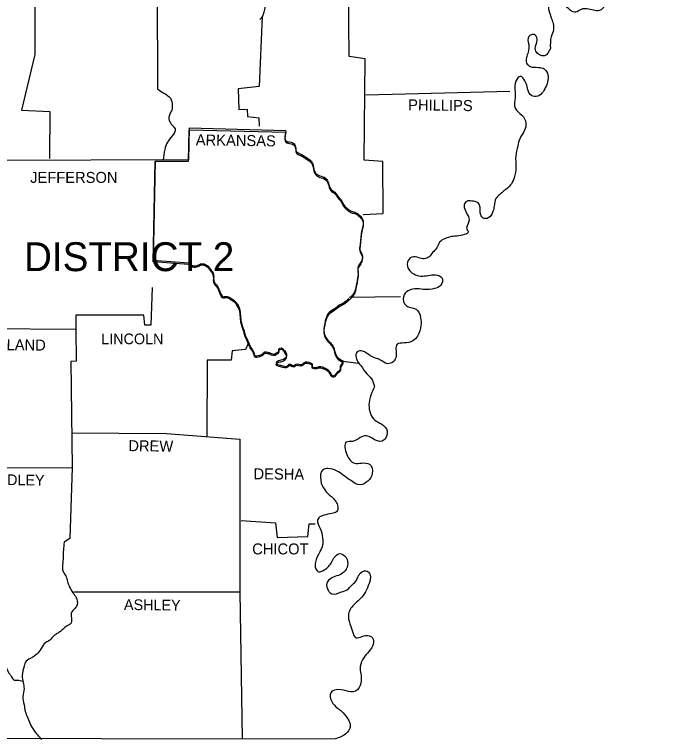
# Model space of a CAD drawing. Extents: x 172 to 3385, y 73 to 2074.
# Drawn here: x 3005.2 to 3257.2, y 1432.7 to 1710.1 of the extents above; entities that cross this region are included whole.
import ezdxf

# ---------------------------------------------------------------- set-up
doc = ezdxf.new("R2010")
doc.units = 0
for name, color, linetype in [('R_Border', 7, 'Continuous'), ('R_Border Prem', 7, 'Continuous'), ('R_Grid', 7, 'Continuous')]:
    doc.layers.add(name, color=color, linetype=linetype)

msp = doc.modelspace()

# ---------------------------------------------------------------- linework, layer by layer
at = {"layer": 'R_Border Prem'}
msp.add_line((3133.42, 1601.94), (3152.99, 1602.24), dxfattribs=at)
for points in [[(3045.86, 1737.06), (3046.05, 1719.55), (3059.85, 1719.25), (3059.95, 1681.68)], [(3007.21, 1732.56), (3012.88, 1732.17), (3012.98, 1694.79), (3007.89, 1673.56), (3018.75, 1673.07), (3018.66, 1655.07)], [(3138.71, 1633.54), (3146.34, 1634.03), (3146.24, 1653.9), (3139.1, 1654.38), (3139.49, 1693.23), (3133.33, 1694.11), (3133.13, 1720.23), (3216.59, 1720.82)], [(3100.06, 1709.37), (3098.89, 1682.56), (3090.86, 1681.68), (3091.06, 1673.76), (3094.29, 1673.85), (3094.39, 1671.11), (3098.79, 1670.63), (3098.89, 1667.4)], [(3139.69, 1679.43), (3194.87, 1680.8)], [(3109.06, 1665.64), (3072.08, 1666.61), (3071.88, 1654.58), (2997.03, 1654.29)], [(3059.06, 1653.99), (3071.88, 1653.99), (3072.08, 1666.03), (3109.06, 1665.05)], [(3059.06, 1653.99), (3058.28, 1616.13), (3071.88, 1615.05)], [(3071.88, 1614.47), (3058.28, 1615.54), (3059.06, 1653.99)], [(3057.99, 1605.66), (3057.4, 1591.28), (3055.15, 1591.28), (3054.76, 1595.09), (3028.73, 1595.09), (3028.73, 1589.61)], [(2993.9, 1589.91), (3028.54, 1589.71)], [(3028.73, 1589.71), (3028.83, 1577.48), (3026.78, 1577.38), (3027.36, 1536.78)], [(3094.87, 1584.53), (3093.7, 1581.88), (3088.51, 1581.4), (3088.22, 1577.87), (3078.93, 1577.87), (3078.83, 1548.62)], [(3105.83, 1580.22), (3106.13, 1580.51), (3106.42, 1580.81), (3106.42, 1580.81)], [(3027.07, 1550.09), (3063.37, 1549.79), (3091.55, 1547.64)], [(3091.55, 1547.64), (3091.55, 1489.13), (3092.33, 1432.87)], [(2983.14, 1536.68), (3027.36, 1536.78)], [(3027.36, 1536.78), (3026.39, 1509.58), (3024.23, 1508.21)], [(3092.04, 1516.43), (3105.15, 1515.65), (3105.73, 1509.97), (3117.57, 1510.36), (3118.06, 1515.16), (3120.31, 1515.16)], [(2769.26, 1512.61), (2769.46, 1433.46), (3128.04, 1432.87)], [(3027.95, 1489.23), (3091.55, 1489.23)]]:
    msp.add_lwpolyline(points, dxfattribs=at)
for points in [[(3252.89, 1794.1), (3253.28, 1791.26), (3251.62, 1788.23), (3251.03, 1785.2), (3251.32, 1782.16), (3248.19, 1780.5), (3245.45, 1778.54), (3247.02, 1776.2), (3249.95, 1774.04), (3252.89, 1772.38), (3254.75, 1770.72), (3255.24, 1766.71), (3255.72, 1764.16), (3256.7, 1760.64), (3257.09, 1758.19), (3255.33, 1755.26), (3253.28, 1754.67), (3251.13, 1755.36), (3248.58, 1755.55), (3246.53, 1753.59), (3245.06, 1750.86), (3243.59, 1748.12), (3242.52, 1745.77), (3241.44, 1743.22), (3239.29, 1740.29), (3236.65, 1739.8), (3233.51, 1739.02), (3231.66, 1736.86), (3231.95, 1733.24), (3233.71, 1730.8), (3235.08, 1727.76), (3236.06, 1725.12), (3235.57, 1721.8), (3234.2, 1719.35), (3232.44, 1717.88), (3231.66, 1714.75), (3230.38, 1712.4), (3229.21, 1711.62), (3226.86, 1711.82), (3224.32, 1712.31), (3222.16, 1712.11), (3220.11, 1711.03), (3218.06, 1711.72), (3215.9, 1714.07), (3214.14, 1715.83), (3212.19, 1716.51), (3210.13, 1715.44), (3209.74, 1712.21), (3210.72, 1708.88), (3211.6, 1704.38), (3210.72, 1701.64), (3210.42, 1697.14)], [(3098.98, 1718.76), (3098.59, 1716.81), (3099.37, 1714.75), (3100.74, 1714.07), (3100.94, 1712.11), (3100.45, 1710.15), (3100.06, 1709.37), (3099.18, 1708.2)], [(3210.42, 1697.14), (3208.17, 1694.3), (3204.85, 1696.06), (3204.85, 1698.41), (3205.34, 1700.86), (3204.16, 1702.42), (3202.11, 1701.74), (3202.11, 1698.71), (3201.91, 1695.77), (3201.32, 1691.56), (3202.69, 1690.29), (3205.83, 1689.9), (3208.08, 1689.31), (3209.45, 1687.06), (3209.35, 1684.32), (3208.27, 1681.68), (3206.71, 1679.53), (3204.26, 1678.75), (3202.3, 1680.02), (3201.52, 1682.56), (3200.64, 1684.81), (3198.98, 1686.48), (3197.22, 1684.62), (3196.82, 1681.19), (3196.92, 1678.26), (3196.92, 1674.25), (3199.47, 1671.6), (3201.03, 1668.57), (3200.54, 1665.83), (3198.68, 1662.6), (3197.9, 1659.77), (3197.12, 1655.95), (3197.22, 1651.74), (3196.53, 1647.63), (3195.16, 1644.89), (3192.62, 1642.64), (3190.95, 1641.18), (3189.58, 1639.71), (3188.9, 1636.77), (3188.41, 1634.72), (3186.55, 1632.27), (3185.08, 1632.08), (3183.91, 1633.05), (3183.52, 1634.72), (3183.52, 1636.38), (3182.74, 1638.04), (3180.29, 1638.73), (3178.33, 1638.63), (3177.45, 1637.26), (3178.72, 1633.45), (3179.21, 1631), (3178.53, 1627.67), (3178.92, 1627.28), (3175.4, 1625.42), (3172.56, 1625.13), (3170.21, 1624.44), (3167.96, 1622.98), (3166.88, 1620.82), (3165.32, 1619.06), (3163.95, 1617.4), (3162.09, 1616.62), (3160.04, 1617.01), (3157.3, 1617.3), (3155.73, 1615.35), (3156.22, 1612.51), (3158.08, 1610.85), (3160.82, 1610.06), (3163.66, 1610.26), (3166.4, 1610.55), (3168.94, 1609.18), (3168.45, 1606.54), (3166, 1605.27), (3162.38, 1604.88), (3159.45, 1605.17), (3155.93, 1604.39), (3154.17, 1602.14), (3155.14, 1598.71), (3158.96, 1597.34), (3160.72, 1594.11), (3160.82, 1591.08), (3159.55, 1587.07), (3157.79, 1585.21), (3154.36, 1584.43), (3151.72, 1583.94), (3151.33, 1579.44), (3150.15, 1577.19), (3148.1, 1576.5), (3145.16, 1577.97), (3143.4, 1578.66), (3141.25, 1579.63), (3138.51, 1581.3), (3136.46, 1581), (3137.04, 1576.7), (3137.24, 1576.5), (3139.59, 1573.27), (3141.94, 1570.73), (3143.01, 1567.7)], [(3059.95, 1681.68), (3062.39, 1680.02), (3064.93, 1678.06), (3065.62, 1675.42), (3065.42, 1673.56), (3064.64, 1672), (3064.45, 1669.55), (3065.62, 1667.79), (3066.7, 1666.32), (3065.62, 1663.68), (3063.76, 1661.23), (3062.78, 1658.49), (3062.1, 1654.38)], [(3109.06, 1665.64), (3109.35, 1661.62), (3111.7, 1661.04), (3112.68, 1659.96), (3113.17, 1657.71), (3114.83, 1656.73), (3117.08, 1655.36), (3118.45, 1654.38), (3119.43, 1652.82), (3120.02, 1650.27), (3121.58, 1648.61), (3123.74, 1647.83), (3125.3, 1645.97), (3126.28, 1643.33), (3127.85, 1642.15), (3129.41, 1640.1), (3130.19, 1639.22), (3131.56, 1636.87), (3132.93, 1635.7), (3133.91, 1635.01), (3135.48, 1634.52), (3137.43, 1633.25), (3138.71, 1631.29), (3138.71, 1629.83), (3138.22, 1627.58), (3137.83, 1625.23), (3137.63, 1622.59), (3137.43, 1620.24), (3138.32, 1618.28), (3137.83, 1615.35), (3136.85, 1613.78), (3136.75, 1611.63), (3136.46, 1608.4), (3136.07, 1606.54), (3135.18, 1603.51), (3133.91, 1601.94)], [(3109.06, 1665.05), (3109.35, 1661.04), (3111.7, 1660.45), (3112.68, 1659.37), (3113.17, 1657.12), (3114.83, 1656.15), (3117.08, 1654.78), (3118.45, 1653.8), (3119.43, 1652.23), (3120.02, 1649.69), (3121.58, 1648.02), (3123.74, 1647.24), (3125.3, 1645.38), (3126.28, 1642.74), (3127.85, 1641.57), (3129.41, 1639.51), (3130.19, 1638.63), (3131.56, 1636.28), (3132.93, 1635.11), (3133.91, 1634.42), (3135.48, 1633.94), (3137.43, 1632.66), (3138.71, 1630.71), (3138.71, 1629.24), (3138.22, 1626.99), (3137.83, 1624.64), (3137.63, 1622), (3137.43, 1619.65), (3138.32, 1617.69), (3137.83, 1614.76), (3136.85, 1613.19), (3136.75, 1611.04), (3136.46, 1607.81), (3136.07, 1605.95), (3135.18, 1602.92), (3133.62, 1601.06)], [(3071.88, 1615.05), (3073.35, 1614.07), (3075.4, 1614.17), (3076.77, 1614.76), (3077.85, 1614.66), (3079.32, 1613.78), (3080.3, 1612.61), (3080.98, 1611.73), (3081.47, 1610.36), (3081.47, 1609.08), (3081.96, 1607.32), (3082.55, 1606.64), (3083.33, 1605.37), (3083.82, 1604.19), (3084.11, 1603.41), (3085.19, 1602.14), (3086.17, 1602.24), (3087.05, 1602.14), (3088.22, 1601.45), (3089.98, 1600.08), (3090.28, 1599.69), (3091.45, 1597.15), (3091.65, 1595.58), (3091.84, 1593.53), (3092.23, 1591.57), (3093.02, 1589.42), (3093.41, 1587.95), (3094.29, 1585.9), (3094.87, 1584.53), (3095.66, 1582.76), (3096.83, 1580.81), (3097.32, 1579.63), (3098.98, 1579.73), (3100.16, 1580.22), (3101.04, 1581), (3102.11, 1580.91), (3103.29, 1580.51), (3104.85, 1580.22), (3105.83, 1580.81), (3106.32, 1581.2), (3106.42, 1582.08), (3107.3, 1582.57), (3108.28, 1581.88), (3109.35, 1580.32), (3109.35, 1579.34), (3108.96, 1578.75), (3107.69, 1577.97), (3105.93, 1577.38), (3105.44, 1576.7), (3107.1, 1575.92), (3109.75, 1575.72), (3110.43, 1576.31), (3112.19, 1575.82), (3112.88, 1576.31), (3115.23, 1576.21), (3116.3, 1576.99), (3118.45, 1576.89), (3119.14, 1576.41), (3119.14, 1575.52), (3120.9, 1575.13), (3122.17, 1575.43), (3123.84, 1574.94), (3125.3, 1574.15), (3126.09, 1573.08), (3127.06, 1571.9), (3127.94, 1572.2), (3128.63, 1573.08), (3130.1, 1574.64), (3130.1, 1575.62), (3130.49, 1576.31), (3130.98, 1577.29)], [(3130.98, 1576.7), (3130.49, 1575.72), (3130.1, 1575.04), (3130.1, 1574.06), (3128.63, 1572.49), (3127.94, 1571.61), (3127.06, 1571.32), (3126.09, 1572.49), (3125.3, 1573.57), (3123.84, 1574.35), (3122.17, 1574.84), (3120.9, 1574.55), (3119.14, 1574.94), (3119.14, 1575.82), (3118.45, 1576.31), (3116.3, 1576.41), (3115.23, 1575.62), (3112.88, 1575.72), (3112.19, 1575.23), (3110.43, 1575.72), (3109.75, 1575.13), (3107.1, 1575.33), (3105.44, 1576.11), (3105.93, 1576.8), (3107.69, 1577.38), (3108.96, 1578.17), (3109.35, 1578.75), (3109.35, 1579.73), (3108.28, 1581.3), (3107.3, 1581.98), (3106.42, 1581.49), (3106.32, 1580.61), (3105.83, 1580.22), (3104.85, 1579.63), (3103.29, 1579.93), (3102.11, 1580.32), (3101.04, 1580.42), (3100.16, 1579.63), (3098.98, 1579.14), (3097.32, 1579.05), (3096.83, 1580.22), (3095.66, 1582.18), (3094.87, 1583.94), (3094.29, 1585.31), (3093.41, 1587.36), (3093.02, 1588.83), (3092.23, 1590.98), (3091.84, 1592.94), (3091.65, 1594.99), (3091.45, 1596.56), (3090.28, 1599.1), (3089.98, 1599.5), (3088.22, 1600.87), (3087.05, 1601.55), (3086.17, 1601.65), (3085.19, 1601.55), (3084.11, 1602.82), (3083.82, 1603.6), (3083.33, 1604.78), (3082.55, 1606.05), (3081.96, 1606.74), (3081.47, 1608.5), (3081.47, 1609.77), (3080.98, 1611.14), (3080.3, 1612.02), (3079.32, 1613.19), (3077.85, 1614.07), (3076.77, 1614.17), (3075.4, 1613.58), (3073.35, 1613.49), (3071.88, 1614.47)], [(3133.23, 1601.35), (3131.17, 1599.69), (3129.41, 1598.71), (3127.55, 1597.34), (3125.3, 1595.68), (3124.23, 1592.84), (3123.64, 1588.93), (3124.42, 1586.58), (3126.18, 1584.53), (3127.36, 1582.86), (3128.24, 1579.93), (3130.39, 1577.87), (3131.08, 1577.58)], [(3133.62, 1601.06), (3131.17, 1599.1), (3129.41, 1598.13), (3127.55, 1596.76), (3125.3, 1595.09), (3124.23, 1592.26), (3123.64, 1588.34), (3124.42, 1585.99), (3126.18, 1583.94), (3127.36, 1582.28), (3128.24, 1579.34), (3130.39, 1577.29), (3131.08, 1576.99)], [(3143.01, 1567.7), (3142.03, 1565.45), (3140.96, 1561.53), (3141.25, 1558.21), (3142.72, 1555.37), (3145.07, 1553.8), (3147.61, 1551.55), (3147.41, 1548.13), (3145.95, 1546.86), (3142.52, 1547.74), (3139.88, 1548.91), (3137.63, 1548.23), (3134.6, 1546.76), (3132.35, 1546.47), (3132.45, 1541.77), (3135.48, 1538.44), (3138.12, 1538.44), (3141.15, 1538.05), (3142.23, 1534.53), (3140.47, 1531.59), (3137.53, 1530.13), (3133.81, 1531.89), (3131.17, 1533.75), (3128.53, 1535.51), (3125.2, 1536.39), (3123.35, 1536), (3122.47, 1531.89), (3124.03, 1528.17), (3126.57, 1525.63), (3128.92, 1522.3), (3128.53, 1519.85), (3126.77, 1519.17), (3123.64, 1518.48), (3121.78, 1517.51), (3121.29, 1516.72), (3122.27, 1513.4), (3123.15, 1509.78), (3123.15, 1507.04), (3122.07, 1504.49), (3120.41, 1500.58), (3120.61, 1498.03), (3121.78, 1496.86), (3123.25, 1497.25), (3125.2, 1498.62), (3126.48, 1500.19), (3127.55, 1502.14), (3129.61, 1503.81), (3132.15, 1502.34), (3132.74, 1499.31), (3131.27, 1496.67), (3129.22, 1495.49), (3126.67, 1494.51), (3124.81, 1492.36), (3125.3, 1489.82), (3126.77, 1488.45), (3130.39, 1489.13), (3132.84, 1490.21), (3134.21, 1491.58), (3135.87, 1493.24), (3136.75, 1494.9), (3138.02, 1496.67), (3140.27, 1497.15), (3141.35, 1495.69), (3140.96, 1492.36), (3139.59, 1489.23), (3137.73, 1486.59), (3135.67, 1484.73), (3133.13, 1480.72), (3133.62, 1477), (3134.6, 1473.97), (3135.97, 1471.62), (3138.32, 1472.11), (3140.96, 1472.4), (3142.52, 1471.13), (3142.33, 1468.39), (3140.37, 1465.75), (3138.51, 1463.2), (3137.53, 1459.68), (3137.92, 1457.24), (3137.92, 1454.98), (3137.14, 1452.54), (3135.77, 1451.17), (3132.15, 1451.27), (3128.34, 1451.66), (3126.28, 1450.48), (3126.67, 1447.16), (3128.92, 1444.71), (3130.49, 1443.44), (3132.74, 1440.7), (3133.72, 1438.45), (3133.42, 1436.49), (3132.05, 1434.83), (3128.04, 1432.87)], [(3024.23, 1508.21), (3023.94, 1505.18), (3023.84, 1502.34), (3023.65, 1499.6), (3023.65, 1497.55), (3024.82, 1495.3), (3025.51, 1493.14), (3026.19, 1491.28), (3027.56, 1488.84), (3028.83, 1486.98), (3029.22, 1484.34), (3028.44, 1482.97), (3026.97, 1480.91), (3026.87, 1477.19), (3025.11, 1476.02), (3022.86, 1474.06), (3021.59, 1473.18), (3020.22, 1472.3), (3018.75, 1470.74), (3016.6, 1469.27), (3015.04, 1466.82), (3013.28, 1464.96), (3011.81, 1463.99), (3009.75, 1462.71), (3008.87, 1460.76), (3008.19, 1457.14), (3008.48, 1454.5), (3008.87, 1452.15), (3008.38, 1449.21), (3008.87, 1445.98), (3009.36, 1443.44), (3010.14, 1441.19), (3011.22, 1438.65), (3012.59, 1436.3), (3015.53, 1432.68)], [(2926.69, 1485.61), (2928.25, 1486.69), (2929.72, 1487.27), (2931.19, 1486.98), (2932.75, 1486.78), (2934.12, 1486.98), (2935.88, 1486.69), (2937.35, 1485.8), (2939.01, 1485.12), (2940.68, 1485.12), (2942.14, 1485.12), (2943.42, 1484.24), (2945.77, 1484.34), (2947.72, 1485.12), (2949.68, 1485.71), (2952.32, 1486), (2954.67, 1484.34), (2956.33, 1482.97), (2957.7, 1481.4), (2958.68, 1479.64), (2959.76, 1478.66), (2961.52, 1477.98), (2962.89, 1477.68), (2964.55, 1477.19), (2965.43, 1476.8), (2966.21, 1474.94), (2967.49, 1472.4), (2969.93, 1471.52), (2972.96, 1472.69), (2975.41, 1473.38), (2977.17, 1473.97), (2978.25, 1474.36), (2979.23, 1474.46), (2978.93, 1474.65), (2980.11, 1474.94), (2981.18, 1474.16), (2981.87, 1473.09), (2983.04, 1471.52), (2984.12, 1470.15), (2985.19, 1469.66), (2986.27, 1470.25), (2987.74, 1469.76), (2989.01, 1469.27), (2990.48, 1468.88), (2991.75, 1468.78), (2993.41, 1468.39), (2994.69, 1467.7), (2995.86, 1467.02), (2997.03, 1465.75), (2998.21, 1463.79), (2998.6, 1462.23), (2999.97, 1460.66), (3001.24, 1460.66), (3003.1, 1458.12), (3003.78, 1457.14), (3005.25, 1455.38), (3006.33, 1455.38), (3008.38, 1454.98)]]:
    msp.add_spline(points, degree=3, dxfattribs=at)
at = {"layer": 'R_Grid'}
msp.add_line((3130.78, 1577.48), (3136.95, 1576.7), dxfattribs=at)

# ---------------------------------------------------------------- texts
at = {"layer": 'R_Border'}
for s, height, rotation, p in [('PHILLIPS', 4.206, 359.3179, (3155.93, 1673.46)), ('ARKANSAS', 4.206, 359.2678, (3074.62, 1660.06)), ('CLEVELAND', 4.207, 359.3377, (2983.73, 1581.88)), ('DREW', 4.206, 359.2258, (3048.79, 1543.04)), ('DESHA', 4.206, 359.3704, (3096.73, 1532.28)), ('BRADLEY', 4.108, 359.1449, (2991.07, 1530.22)), ('ASHLEY', 4.109, 359.2361, (3047.13, 1482.28))]:
    msp.add_text(s, height=height, rotation=rotation, dxfattribs=at).set_placement(p)
for s, height, p in [('JEFFERSON', 4.207, (3011.22, 1645.68)), ('LINCOLN', 4.109, (3038.42, 1583.94)), ('CHICOT', 4.207, (3096.24, 1503.51))]:
    msp.add_text(s, height=height, dxfattribs=at).set_placement(p)
at = {"layer": 'R_Grid'}
msp.add_text('DISTRICT 2', height=11.056, dxfattribs=at).set_placement((3008.87, 1611.92))

doc.saveas('drawing.dxf')
